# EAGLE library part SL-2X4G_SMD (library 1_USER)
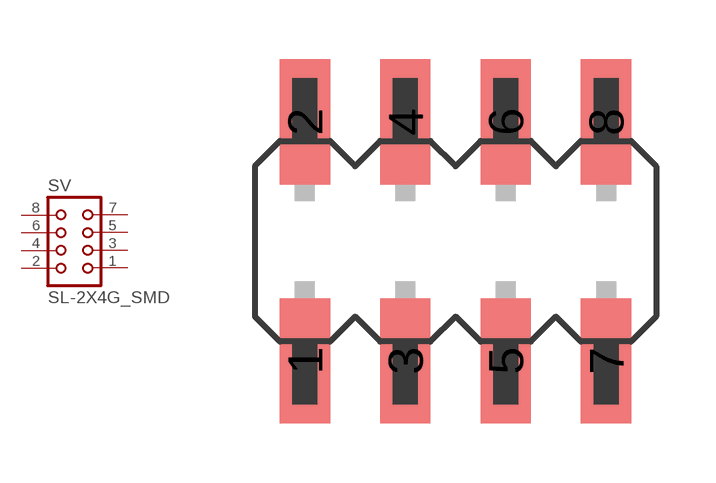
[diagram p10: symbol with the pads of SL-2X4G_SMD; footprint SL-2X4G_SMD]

Designator prefix SV

## SL-2X4G_SMD  [SL-2X4G_SMD]
1  1  pas
2  2  pas
3  3  pas
4  4  pas
5  5  pas
6  6  pas
7  7  pas
8  8  pas

## Footprint SL-2X4G_SMD (pad centres in mm)
smd 1.27 x 3.17: 1 -3.81,-3.027; 2 -3.81,3.027; 3 -1.27,-3.027; 4 -1.27,3.027; 5 1.27,-3.027; 6 1.27,3.027; 7 3.81,-3.027; 8 3.81,3.027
